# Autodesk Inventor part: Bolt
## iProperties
Created: 2002-02
Part Number: Bolt
Document SubType Name: Modeling
Designer: ***
Control State: 0
Master: False
Checked Out: False
Shininess: 77.0
Length Units: 11269
Angle Units: 11279
Time Units: 11290
Mass Units: 11283
Length Display Precision: 3
Angle Display Precision: 2
Density: 0.0
Volumn: 0.0
Area: 0.0
PropertySet Name: Model Information
Author: ***
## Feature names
1. Extrusion1
2. Fillet1
3. Extrusion2
4. Extrusion3
